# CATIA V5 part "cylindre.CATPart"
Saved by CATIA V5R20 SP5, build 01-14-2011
Part number: cylindre
Bounding box of the stored display mesh (mm): x -24.338 to 65.824, y 0 to 310, z 1016.323 to 1195.939
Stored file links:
  M:\EU_thinkMotion\IAO_2010\iao\IAO_MMS_Groupe2\IAO_MMS_Groupe2\rwatrin\rwatrin\cylindre.CATPart
  M:\EU_thinkMotion\IAO_2010\iao\IAO_MMS_Groupe2\IAO_MMS_Groupe2\rwatrin\rwatrin\bati.CATPart
  M:\EU_thinkMotion\IAO_2010\iao\IAO_MMS_Groupe2\IAO_MMS_Groupe2\rwatrin\rwatrin\mecanisme_iao_optimise.CATProduct
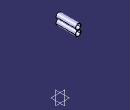
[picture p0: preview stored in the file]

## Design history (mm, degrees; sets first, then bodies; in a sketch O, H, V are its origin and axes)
Parameters
  longueur_cyl = 310 mm
  `tige_vérin` = 300 mm
  `hauteur cyl bas` = 201.91 mm
Set1
  Line1: linked copy from another document
  Plane1: linked copy from another document
Set2
  Point1: type Center, Curve edge [end face of Pad1 | face of Hole1]
  Point2: type Center, Curve edge [end face of Pad1 | face of Hole2]
  Line2: type PtPt, FirstPoint Point2, SecondPoint Point1
  Plane2: type OffsetPt, RefPlane end face of Pad1, RefPoint Point1
  Plane3: type Angle, RefPlane Plane2, Direction Line2, Angle 90
Body1 (main body)
  Sketch1 on zx-plane, origin (0, 0, 0), H (-1, 0, 0), V (0, 0, 1)
    circle A1 centre (-20.8235, 1061.1311) radius 45
    point P1 (-20.8235, 1061.1311)
    circle A2 centre (-20.6621, 1151.131) radius 45
    reference intersected line E1 through (0, 859.2211) direction (1, 0) from Plane1
    radius A2 = 45
    radius A1 = 45
    distance P1 E1 = 201.91 {= `hauteur cyl bas`}
    tangency: A2 A1
  Pad1: profile Sketch1, direction (0, 1, 0), length 310 {= longueur_cyl}
  Sketch2 on end face of Pad1, origin (20.0775, 310, 166.2559), H (1, 0, 0), V (0, 0, -1)
    point P1 (0.5846, -984.8751)
    reference projected circle E1 centre (0.5846, -984.8751) radius 45 from edge [face of Pad1 from Sketch1.A2 | end face of Pad1]
    concentricity: P1 E1
  Hole1: placed by Sketch2, at (20.6621, 310, 1151.131) direction (0, -1, 0), diameter 80, depth 300 {= `tige_vérin`}
  Sketch3 on end face of Pad1, origin (9.9291, 310, 63.2367), H (1, 0, 0), V (0, 0, -1)
    point P1 (10.8945, -997.8945)
    reference projected circle E1 centre (10.8945, -997.8945) radius 45 from edge [face of Pad1 from Sketch1.A1 | end face of Pad1]
    concentricity: P1 E1
  Hole2: placed by Sketch3, at (20.8235, 310, 1061.1311) direction (0, -1, 0), diameter 80, depth 300 {= `tige_vérin`}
